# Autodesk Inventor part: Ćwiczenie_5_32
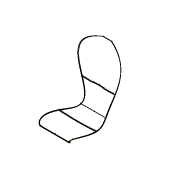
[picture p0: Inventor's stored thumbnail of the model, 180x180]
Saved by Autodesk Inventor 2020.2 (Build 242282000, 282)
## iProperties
Created: 2005-04
Part Number: Ćwiczenie_5_32
Document SubType Name: Modeling
Designer: F.Stasiak
Manufacturer: Standard
Standards Organization: Custom
Density: 1 g/cm^3
Material: Ogólny
Appearance: Domyślna
Manager: www.cadconsulting.pl
Company: Fabian Stasiak CAD Consulting
Author: F.Stasiak
Subject: Zbiór ćwiczeń. Autodesk Inventor 2020. Kurs podstawowy
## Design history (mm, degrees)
sketch "Szkic środkowy" dims "d61" = 8
  geometry: L1 (132.362, 632.238)-(181.02, 729.553) reference; L2 (-471.984, -56.978)-(-471.984, 51.824) reference; A1 r 244.705 centre (375.562, 571.46) between (185.656, 725.785) and (138.158, 630.789); A2 r 79.282 centre (-392.702, -2.577) between (-458.075, 42.28) and (-458.075, -47.433); 10 further points
  constraints: 4 end point, 4 midpoint, 3 vertical, 2 centre point, 2 point on circle, 1 coincident, 21 other
  dimensions: "d46" = 5 dimension on L1.start L1.end; "d47" = 5 dimension on L2.start L2.end
node "Płaszczyzna konstrukcyjna3"
node "Płaszczyzna konstrukcyjna4"
node "Płaszczyzna konstrukcyjna5"
node "Płaszczyzna konstrukcyjna10"
node "Płaszczyzna konstrukcyjna11"
sketch "Profil 1"
  geometry: L1 (-175, 0)-(175, 0) reference; L2 (175, 0)-(175, -8) reference; L3 (175, -8)-(-175, -8) reference; L4 (-175, -8)-(-175, 0) reference; 2 further points
  constraints: 8 end point, 3 horizontal, 2 parallel, 2 vertical, 1 coincident, 1 midpoint, 1 perpendicular
sketch "Profil 2"
  geometry: L1 (225, 8)-(-225, 8) reference; L2 (-225, 8)-(-225, 0) reference; L3 (-225, 0)-(225, 0); L4 (225, 0)-(225, 8) reference; L5 (-224.433, 15.98)-(-225, 8) reference; L6 (224.433, 15.98)-(225, 8) reference; 2 further points
  constraints: 12 end point, 2 horizontal, 2 parallel, 2 vertical, 1 coincident, 1 horizontal alignment, 1 midpoint, 1 perpendicular, 10 other
sketch "Profil 3"
  geometry: L1 (150, 16)-(-150, 16) reference; L2 (-150, 16)-(-150, 0) reference; L3 (-150, 0)-(150, 0) reference; L4 (150, 0)-(150, 16) reference; L5 (-150, 16)-(-148.331, 23.824) reference; L6 (150, 16)-(148.331, 23.824) reference; 2 further points
  constraints: 12 end point, 3 horizontal, 2 parallel, 2 vertical, 1 coincident, 1 horizontal alignment, 1 midpoint, 1 perpendicular, 10 other
sketch "Profil 4"
  geometry: L1 (-200, 0)-(200, 0) reference; L2 (200, 0)-(200, 16) reference; L3 (200, 16)-(-200, 16) reference; L4 (-200, 16)-(-200, 0) reference; L5 (-200, 8)-(200, 8) reference; L6 (-200, 8)-(-200, 16) reference; L7 (146.39, 8)-(253.61, 8); L8 (-253.61, 8)-(-146.39, 8); L9 (200, 16)-(200, 8) reference; A1 r 718.335 centre (200, 726.335) between (146.539, 9.992) and (253.461, 9.992); A2 r 718.335 centre (-200, 726.335) between (-253.461, 9.992) and (-146.539, 9.992); 4 further points
  constraints: 18 end point, 8 horizontal, 7 midpoint, 4 vertical, 3 parallel, 2 centre point, 2 perpendicular, 2 point on circle, 2 point on line, 1 coincident, 1 horizontal alignment, 13 other
  dimensions: "d51" = 15 dimension on L7.start L7.end; "d52" = 15 dimension on L8.start L8.end
sketch "Profil 5"
  geometry: L1 (50, 8)-(-50, 8) reference; L2 (-50, 8)-(-50, 0) reference; L3 (-50, 0)-(50, 0) reference; L4 (50, 0)-(50, 8) reference
  constraints: 8 end point, 3 horizontal, 2 parallel, 2 vertical, 1 perpendicular
node "Płaszczyzna konstrukcyjna12"
node "Płaszczyzna konstrukcyjna13"
node "Płaszczyzna konstrukcyjna14"
node "Płaszczyzna konstrukcyjna15"
node "Płaszczyzna konstrukcyjna16"
node "Płaszczyzna konstrukcyjna17"
node "Oś konstrukcyjna3"
node "Punkt konstrukcyjny32"
node "Punkt konstrukcyjny33"
node "Punkt konstrukcyjny39"
node "Oś konstrukcyjna6"
node "Punkt konstrukcyjny40"
node "Punkt konstrukcyjny41"
sketch "Prowadnica 1"
sketch "Prowadnica 2"
sketch "Prowadnica 3"
sketch "Prowadnica 4"
node "Korpusy bryłowe"
node "Korpusy powierzchniowe"
